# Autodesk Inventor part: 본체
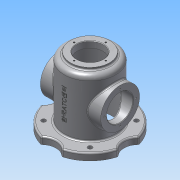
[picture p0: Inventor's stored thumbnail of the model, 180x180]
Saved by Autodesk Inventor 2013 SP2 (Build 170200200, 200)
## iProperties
Created: 2026-07
Part Number: 본체
Material: 알루미늄 6061
Document SubType Name: Modeling
Designer: 601
Mass: 1509.35 g
Surface Area: 1242.71 cm^2
Volume: 556.956 cm^3
Density: 2.71 g/cm^3
Author: 601
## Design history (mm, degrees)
sketch "스케치1"
  geometry: L1 (0, 0)-(0, 137); L2 (0, 137)-(-40, 137); L3 (-40, 137)-(-40, 132); L4 (-40, 132)-(-43, 132); L5 (-53, 122)-(-53, 14); L6 (-53, 14)-(-82, 14); L7 (-82, 14)-(-82, 0); L8 (-82, 0)-(0, 0); A1 r 10 centre (-43, 122) between (-43, 132) and (-53, 122)
  constraints: 16 end point, 4 perpendicular, 3 parallel, 2 point on circle, 2 tangent, 1 centre point, 1 vertical
  dimensions: "d0" = 137 distance of L1.start L1.end; "d1" = 5 distance of L2.end L3.end; "d3" = 14 distance of L6.end L7.end; "d4" = 80 diameter of L3 L1; "d5" = 106 diameter of L5 L1; "d6" = 164 diameter of L7 L1; "d7" = 10 radius of A1
revolve "회전1" sketch "스케치1" stored, may be unused: angle "d8" = 90 deg
sketch "스케치2"
  geometry: C1 r 82 at (0, 0) reference; C2 r 45 at (0, 0)
  constraints: 1 centre point, 1 coincident
  dimensions: "d9" = 90 diameter of C2
extrude "돌출1" cut sketch "스케치2" distance "d10" = 124; taper "d11" = 0 deg
sketch "스케치3"
  geometry: C1 r 40 at (0, 0) reference; C2 r 27 at (0, 0)
  constraints: 1 centre point, 1 coincident
  dimensions: "d12" = 54 diameter of C2
extrude "돌출2" cut sketch "스케치3" stored distance "d13" = 124; taper "d14" = 0 deg
sketch "스케치4"
  geometry: C1 r 27 at (0, 0) reference; 1 further point
  constraints: 1 vertical alignment
  dimensions: "d15" = 32.5 distance of C1.centre point (0, 32.5)
hole "구멍1" sketch "스케치4" at (0, 32.5) diameter "d16" = 3.242; stored, may be unused: countersink angle "d20" = 90 deg, drill point angle "d22" = 118 deg; dims "d17" = 8, "d18" = 4, "d19" = 2, "d21" = 10
node "작업 평면2"
  node "작업 평면1"
sketch "스케치5"
  geometry: C1 r 40 at (0, 0); 1 further point
  constraints: 1 centre point, 1 horizontal alignment
  dimensions: "d28" = 80 diameter of C1; "d29" = 68 distance of point (68, 0) C1.centre
extrude "돌출3" join sketch "스케치5" stored distance "d30" = 124; taper "d31" = 0 deg
node "작업 평면4"
sketch "스케치6"
  geometry: C1 r 40 at (0, 0); 1 further point
  constraints: 1 centre point, 1 horizontal alignment
  dimensions: "d33" = 80 diameter of C1; "d34" = 68 distance of point (-68, 0) C1.centre
extrude "돌출4" join sketch "스케치6" stored distance "d35" = 124; taper "d36" = 0 deg
sketch "스케치7"
  geometry: C1 r 40 at (0, 0) reference; C2 r 27 at (0, 0); 1 further point
  constraints: 1 centre point, 1 coincident
  dimensions: "d37" = 54 diameter of C2
extrude "돌출5" cut sketch "스케치7" stored distance "d38" = 124; taper "d39" = 0 deg
sketch "스케치8"
  geometry: C1 r 27 at (0, 0) reference; 2 further points
  constraints: 1 vertical alignment
  dimensions: "d40" = 32.5 distance of C1.centre point (0, 32.5)
hole "구멍2" sketch "스케치8" at (0, 32.5) diameter "d41" = 3.242; stored, may be unused: countersink angle "d45" = 90 deg, drill point angle "d47" = 118 deg; dims "d42" = 8, "d43" = 4, "d44" = 2, "d46" = 10
sketch "스케치9"
  geometry: C1 r 53 at (0, 0) reference; C2 r 30 at (-100, 0)
  constraints: 1 centre point, 1 horizontal alignment
  dimensions: "d51" = 60 diameter of C2; "d52" = 100 distance of C1.centre C2.centre
extrude "돌출6" cut sketch "스케치9" stored distance "d53" = 124; taper "d54" = 0 deg
sketch "스케치10" dims "d57" = 135
  geometry: L1 (0, 0)-(0, 82); L2 (0, 0)-(-57.983, 57.983); C1 r 53 at (0, 0) reference; C2 r 4.5 at (-47.73, 47.73); A1 r 82 centre (0, 0) between (-79.12, -21.541) and (-79.12, 21.541) reference; 1 further point
  constraints: 4 end point, 2 point on circle, 1 centre point, 1 coincident, 1 point on line, 1 vertical, 3 other
  dimensions: "d56" = 45 deg angle of L1 L2; "d58" = 9 diameter of C2
extrude "돌출7" cut sketch "스케치10" stored distance "d59" = 124; taper "d60" = 0 deg
chamfer "모따기1" distance "d64" = 1; stored, may be unused: second distance "d65" = 2, angle "d66" = 45 deg
fillet "모깎기1" dims "d67" = 3
fillet "모깎기2" dims "d68" = 3
fillet "모깎기3" dims "d69" = 3
fillet "모깎기4" dims "d70" = 3
node "작업 평면5"
sketch "스케치11"
  geometry: 2 further points
  constraints: 1 vertical alignment, 1 other
  dimensions: "d71" = 70 distance of point (0, -68) point (0, 2)
feature "엠보싱1" sketch "스케치11" dims "d0" = 137, "d1" = 5, "d3" = 14, "d4" = 80, "d5" = 106, "d6" = 164, "d7" = 10, "d72" = 0.5, "d73" = 0
node "솔리드1"
pattern_circular "원형 패턴1" dims angle "d24" = 360 deg
pattern_circular "원형 패턴2" dims angle "d49" = 360 deg
mirror "대칭1"
pattern_circular "원형 패턴3" dims angle "d62" = 360 deg
other parameters: "d26" = -9, "d32" = -124
